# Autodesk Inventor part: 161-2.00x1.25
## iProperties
Created: 2007-06
Part Number: 161-2.00x1.25
Document SubType Name: Modeling
Designer: btaylor
Density: 1 g/cm^3
Author: btaylor
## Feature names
1. Extrusion1
2. Extrusion2
3. Extrusion3
4. Extrusion4
5. Extrusion5
6. Fillet1
7. Fillet2
8. Fillet3
9. Fillet4
10. Hole2
11. Hole3
12. Hole4
13. Extrusion6
14. Extrusion7
15. Fillet6
16. Fillet11
17. Fillet12
18. Fillet13
19. Chamfer3
20. Chamfer4
21. Chamfer5
22. Fillet14
23. Fillet15
24. Fillet16
